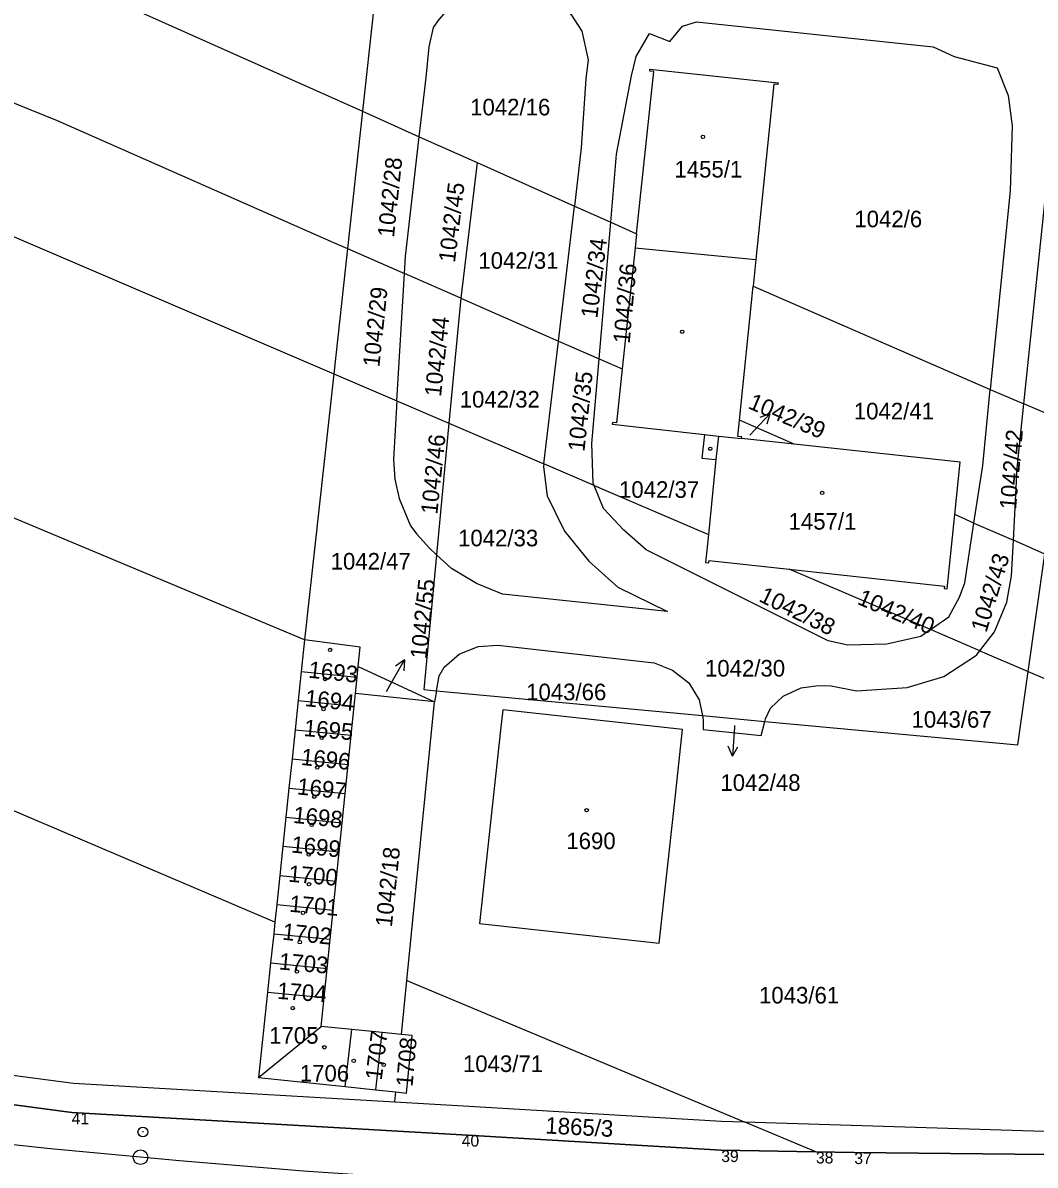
# Model space of a CAD drawing. Extents: x -779330 to -774454, y -1144748 to -1142831.
# Drawn here: x -775422.9 to -775319.2, y -1144462.2 to -1144345.1 of the extents above; entities that cross this region are included whole.
import ezdxf

# ---------------------------------------------------------------- set-up
doc = ezdxf.new("R2010")
doc.units = 0
for name, color, linetype in [('Hranice parcel', 7, 'Continuous'), ('Parcelní čísla', 7, 'Continuous'), ('Pop  PČ popisy', 7, 'Continuous'), ('SŽDC', 7, 'Continuous'), ('Vnitřní kresba', 7, 'Continuous'), ('Vrstva 1', 7, 'Continuous'), ('Vrstva 53', 7, 'Continuous'), ('Vrstva 60', 7, 'Continuous'), ('Vrstva 7', 7, 'Continuous'), ('Značky budov', 7, 'Continuous')]:
    doc.layers.add(name, color=color, linetype=linetype)

msp = doc.modelspace()

# ---------------------------------------------------------------- linework, layer by layer
at = {"layer": 'Hranice parcel'}
for p, q in [((-775388.13, -1144354.18), (-775389.67, -1144368.26)), ((-775388.13, -1144354.18), (-775382.3, -1144356.79)), ((-775382.3, -1144356.79), (-775376.38, -1144359.43)), ((-775376.38, -1144359.43), (-775378.05, -1144373.35)), ((-775376.38, -1144359.43), (-775366.41, -1144363.89)), ((-775368.04, -1144377.73), (-775366.41, -1144363.89)), ((-775366.41, -1144363.89), (-775362.68, -1144365.56)), ((-775363.88, -1144379.55), (-775362.68, -1144365.56)), ((-775362.68, -1144365.56), (-775360.03, -1144366.75)), ((-775389.67, -1144368.26), (-775391.08, -1144381.09)), ((-775389.67, -1144368.26), (-775383.83, -1144370.82)), ((-775384.59, -1144383.87), (-775383.83, -1144370.82)), ((-775378.05, -1144373.35), (-775383.83, -1144370.82)), ((-775349.49, -1144385.85), (-775348.09, -1144372.09)), ((-775348.09, -1144372.09), (-775323.77, -1144382.71)), ((-775378.05, -1144373.35), (-775379.26, -1144386.15)), ((-775378.05, -1144373.35), (-775368.04, -1144377.73)), ((-775369.53, -1144390.33), (-775368.04, -1144377.73)), ((-775368.04, -1144377.73), (-775363.88, -1144379.55)), ((-775363.88, -1144379.55), (-775361.5, -1144380.59)), ((-775391.08, -1144381.09), (-775394.06, -1144408.34)), ((-775391.08, -1144381.09), (-775384.59, -1144383.87)), ((-775323.77, -1144382.71), (-775320.33, -1144384.17)), ((-775384.59, -1144383.87), (-775379.26, -1144386.15)), ((-775317.45, -1144385.39), (-775320.33, -1144384.17)), ((-775379.26, -1144386.15), (-775380.53, -1144399.63)), ((-775379.26, -1144386.15), (-775369.53, -1144390.33)), ((-775343.88, -1144388.31), (-775349.49, -1144385.85)), ((-775343.88, -1144388.31), (-775349.26, -1144387.73)), ((-775364.38, -1144392.54), (-775369.53, -1144390.33)), ((-775364.38, -1144392.54), (-775352.65, -1144397.57)), ((-775325.45, -1144396.38), (-775327.4, -1144395.52)), ((-775325.45, -1144396.38), (-775321.4, -1144398.15)), ((-775318.18, -1144399.56), (-775321.4, -1144398.15)), ((-775329.91, -1144407.31), (-775344.4, -1144401.1)), ((-775324.84, -1144409.48), (-775329.91, -1144407.31)), ((-775394.06, -1144408.34), (-775394.4, -1144411.6)), ((-775324.84, -1144409.48), (-775319.89, -1144411.6)), ((-775394.4, -1144411.6), (-775394.72, -1144414.58)), ((-775394.4, -1144411.6), (-775388.68, -1144412.17)), ((-775388.68, -1144412.17), (-775388.57, -1144411.1)), ((-775388.57, -1144411.1), (-775380.75, -1144414.72)), ((-775319.89, -1144411.6), (-775313.07, -1144414.53)), ((-775388.84, -1144413.84), (-775388.68, -1144412.17)), ((-775388.98, -1144415.16), (-775388.84, -1144413.84)), ((-775380.75, -1144414.72), (-775388.84, -1144413.84)), ((-775380.54, -1144413.57), (-775380.75, -1144414.72)), ((-775380.54, -1144413.57), (-775353.29, -1144416.11)), ((-775394.72, -1144414.58), (-775395.03, -1144417.57)), ((-775394.72, -1144414.58), (-775388.98, -1144415.16)), ((-775389.29, -1144418.14), (-775388.98, -1144415.16)), ((-775383.57, -1144443.27), (-775380.75, -1144414.72)), ((-775353.29, -1144416.11), (-775346.87, -1144416.71)), ((-775395.03, -1144417.57), (-775395.35, -1144420.56)), ((-775395.03, -1144417.57), (-775389.29, -1144418.14)), ((-775389.59, -1144421.13), (-775389.29, -1144418.14)), ((-775395.35, -1144420.56), (-775395.66, -1144423.55)), ((-775395.35, -1144420.56), (-775389.59, -1144421.13)), ((-775389.9, -1144424.12), (-775389.59, -1144421.13)), ((-775395.66, -1144423.55), (-775395.97, -1144426.53)), ((-775395.66, -1144423.55), (-775389.9, -1144424.12)), ((-775390.2, -1144427.1), (-775389.9, -1144424.12)), ((-775395.97, -1144426.53), (-775396.29, -1144429.52)), ((-775395.97, -1144426.53), (-775390.2, -1144427.1)), ((-775390.52, -1144430.09), (-775390.2, -1144427.1)), ((-775396.29, -1144429.52), (-775396.6, -1144432.51)), ((-775396.29, -1144429.52), (-775390.52, -1144430.09)), ((-775390.82, -1144433.08), (-775390.52, -1144430.09)), ((-775396.6, -1144432.51), (-775396.92, -1144435.49)), ((-775396.6, -1144432.51), (-775390.82, -1144433.08)), ((-775391.12, -1144436.06), (-775390.82, -1144433.08)), ((-775396.92, -1144435.49), (-775397.11, -1144437.29)), ((-775396.92, -1144435.49), (-775391.12, -1144436.06)), ((-775391.44, -1144439.04), (-775391.12, -1144436.06)), ((-775397.11, -1144437.29), (-775397.23, -1144438.48)), ((-775397.23, -1144438.48), (-775397.55, -1144441.47)), ((-775397.23, -1144438.48), (-775391.44, -1144439.04)), ((-775391.74, -1144442.03), (-775391.44, -1144439.04)), ((-775397.55, -1144441.47), (-775397.86, -1144444.46)), ((-775397.55, -1144441.47), (-775391.74, -1144442.03)), ((-775392.05, -1144445.02), (-775391.74, -1144442.03)), ((-775384.12, -1144448.81), (-775383.57, -1144443.27)), ((-775383.57, -1144443.27), (-775348.99, -1144457.75)), ((-775397.86, -1144444.46), (-775398.78, -1144453.2)), ((-775397.86, -1144444.46), (-775392.05, -1144445.02)), ((-775392.35, -1144448), (-775392.05, -1144445.02)), ((-775398.78, -1144453.2), (-775392.35, -1144448)), ((-775389.23, -1144448.31), (-775392.35, -1144448)), ((-775389.89, -1144454.15), (-775389.23, -1144448.31)), ((-775386.1, -1144448.62), (-775389.23, -1144448.31)), ((-775386.75, -1144454.48), (-775386.1, -1144448.62)), ((-775384.12, -1144448.81), (-775386.1, -1144448.62)), ((-775398.78, -1144453.2), (-775389.89, -1144454.15)), ((-775389.89, -1144454.15), (-775386.75, -1144454.48)), ((-775386.75, -1144454.48), (-775384.7, -1144454.7)), ((-775384.8, -1144455.7), (-775384.7, -1144454.7)), ((-775348.99, -1144457.75), (-775318.25, -1144458.71)), ((-775341.64, -1144460.83), (-775348.99, -1144457.75))]:
    msp.add_line(p, q, dxfattribs=at)
for points in [[(-775607.93, -1144251.93), (-775592.73, -1144265.24), (-775577.44, -1144273.94), (-775563.67, -1144281.5), (-775543.76, -1144290.79), (-775411.19, -1144343.87), (-775388.13, -1144354.18)], [(-775632.59, -1144258.06), (-775621.58, -1144265.67), (-775577.27, -1144289.87), (-775522.49, -1144313.33), (-775419.42, -1144355.11), (-775391.09, -1144367.64), (-775389.67, -1144368.26)], [(-775657.22, -1144264.36), (-775641.76, -1144273.65), (-775618.95, -1144284.54), (-775447.05, -1144357.1), (-775391.08, -1144381.09)], [(-775394.06, -1144408.34), (-775619.55, -1144313.89), (-775660.82, -1144292.56), (-775671.23, -1144286.27), (-775688.22, -1144274.1)], [(-775397.11, -1144437.29), (-775575.13, -1144361.42), (-775643.03, -1144333.5), (-775681.69, -1144314.82), (-775705.2, -1144302.37), (-775726.91, -1144287.21)], [(-775352.89, -1144334.93), (-775353.07, -1144336.72), (-775363.07, -1144335.42), (-775385.03, -1144333.14), (-775385.87, -1144333.51), (-775388.13, -1144354.18)], [(-775382.3, -1144356.79), (-775381.59, -1144350.71), (-775381.29, -1144347.59), (-775380.83, -1144345.6), (-775380.26, -1144344.77), (-775379.26, -1144343.66), (-775378.34, -1144342.94), (-775376.9, -1144342.31), (-775374.94, -1144341.74), (-775371.99, -1144341.37), (-775370.97, -1144341.43), (-775368.36, -1144342.85), (-775366.76, -1144344.24), (-775365.64, -1144345.98), (-775364.98, -1144348.92), (-775365.24, -1144350.84), (-775365.71, -1144357.91), (-775366.41, -1144363.89)], [(-775362.68, -1144365.56), (-775362.08, -1144358.58), (-775360.56, -1144350.54), (-775360.06, -1144348.55), (-775358.72, -1144346.19), (-775356.63, -1144347.01), (-775355.33, -1144345.46), (-775353.88, -1144345), (-775329.64, -1144347.57), (-775327.49, -1144348.55), (-775323.08, -1144349.72), (-775321.94, -1144352.56), (-775321.52, -1144355.68), (-775321.75, -1144362.33), (-775323.77, -1144382.71)], [(-775360.03, -1144366.75), (-775358.26, -1144350.1), (-775358.68, -1144350.06), (-775358.66, -1144349.86), (-775345.53, -1144351.28), (-775345.55, -1144351.45), (-775345.97, -1144351.4), (-775347.81, -1144369.38), (-775348.09, -1144372.09)], [(-775320.33, -1144384.17), (-775318.15, -1144363.22), (-775316.68, -1144354.8), (-775314.36, -1144350.65), (-775311.52, -1144351.07), (-775309.28, -1144350.28), (-775307.1, -1144350.08), (-775278.88, -1144352.91), (-775272.68, -1144353.77), (-775264.39, -1144354.9), (-775253.71, -1144357.11), (-775245.99, -1144358.92)], [(-775383.83, -1144370.82), (-775383.73, -1144369.08), (-775382.3, -1144356.79)], [(-775360.03, -1144366.75), (-775360.18, -1144368.18), (-775361.5, -1144380.59)], [(-775364.38, -1144392.54), (-775364.48, -1144392.29), (-775364.63, -1144388.23), (-775363.88, -1144379.55)], [(-775361.5, -1144380.59), (-775362.09, -1144386.13), (-775362.51, -1144386.08), (-775362.52, -1144386.26), (-775353.06, -1144387.31)], [(-775325.45, -1144396.38), (-775324.54, -1144390.49), (-775323.77, -1144382.71)], [(-775384.59, -1144383.87), (-775384.94, -1144389.87), (-775384.8, -1144391.89), (-775384.35, -1144393.86), (-775383.2, -1144396.68), (-775382.56, -1144397.52), (-775381.24, -1144398.97), (-775380.53, -1144399.63)], [(-775321.4, -1144398.15), (-775321.01, -1144390.75), (-775320.33, -1144384.17)], [(-775349.26, -1144387.73), (-775349.24, -1144387.55), (-775349.66, -1144387.5), (-775349.49, -1144385.85)], [(-775353.06, -1144387.31), (-775353.33, -1144389.73), (-775351.89, -1144389.87), (-775352.65, -1144397.57)], [(-775353.06, -1144387.31), (-775351.65, -1144387.47), (-775349.26, -1144387.73)], [(-775327.4, -1144395.52), (-775326.85, -1144390.15), (-775343.88, -1144388.31)], [(-775369.53, -1144390.33), (-775369.56, -1144390.62), (-775369.2, -1144393.61), (-775367.43, -1144397.22), (-775364.92, -1144400.28), (-775361.96, -1144402.96), (-775356.85, -1144405.46), (-775373.79, -1144403.67), (-775376.43, -1144402.59), (-775378.99, -1144401.06), (-775380.53, -1144399.63)], [(-775329.91, -1144407.31), (-775330.89, -1144408), (-775334.37, -1144408.8), (-775338.37, -1144408.89), (-775340.4, -1144408.45), (-775359.06, -1144399.13), (-775361.34, -1144397.12), (-775363.43, -1144394.91), (-775364.38, -1144392.54)], [(-775344.4, -1144401.1), (-775328.46, -1144402.84), (-775328.49, -1144403.09), (-775328.19, -1144403.13), (-775327.4, -1144395.52)], [(-775329.91, -1144407.31), (-775328.04, -1144405.99), (-775326.93, -1144403.97), (-775326.4, -1144402.5), (-775325.45, -1144396.38)], [(-775352.65, -1144397.57), (-775352.95, -1144400.44), (-775352.62, -1144400.47), (-775352.59, -1144400.21), (-775344.4, -1144401.1)], [(-775324.84, -1144409.48), (-775323.33, -1144407.52), (-775322.07, -1144404.48), (-775321.59, -1144401.79), (-775321.4, -1144398.15)], [(-775380.53, -1144399.63), (-775381.84, -1144413.45), (-775380.54, -1144413.57)], [(-775388.57, -1144411.1), (-775388.36, -1144409.09), (-775394.06, -1144408.34)], [(-775380.54, -1144413.57), (-775380.26, -1144412.04), (-775379.75, -1144411.14), (-775378.21, -1144409.82), (-775376.28, -1144409.05), (-775374.25, -1144408.91), (-775358.23, -1144410.71), (-775356.36, -1144411.47), (-775354.67, -1144412.76), (-775353.62, -1144414.5), (-775353.29, -1144416.11)], [(-775346.87, -1144416.71), (-775346.8, -1144416.45), (-775346.3, -1144415.37), (-775344.99, -1144414.12), (-775343.17, -1144413.29), (-775341.43, -1144413.02), (-775340.07, -1144413.06), (-775337.49, -1144413.57), (-775332.31, -1144413.25), (-775328.54, -1144412.12), (-775325.18, -1144409.92), (-775324.84, -1144409.48)], [(-775346.87, -1144416.71), (-775320.96, -1144419.12), (-775319.89, -1144411.6)], [(-775355.32, -1144417.54), (-775373.75, -1144415.54), (-775373.98, -1144417.62), (-775376.13, -1144437.44), (-775357.7, -1144439.44), (-775356.16, -1144425.25), (-775355.32, -1144417.54)], [(-775353.29, -1144416.11), (-775353.2, -1144416.54), (-775353.2, -1144417.56), (-775347.25, -1144418.15), (-775346.87, -1144416.71)], [(-775384.7, -1144454.7), (-775383.62, -1144454.82), (-775383.02, -1144448.92), (-775384.12, -1144448.81)], [(-775436.47, -1144451.33), (-775417.75, -1144453.81), (-775384.8, -1144455.7)], [(-775341.64, -1144460.83), (-775351.35, -1144460.68), (-775377.95, -1144459.1), (-775417.93, -1144456.81), (-775426.17, -1144455.72)], [(-775384.8, -1144455.7), (-775377.77, -1144456.11), (-775351.31, -1144457.68), (-775348.99, -1144457.75)], [(-775254.16, -1144459.9), (-775301.48, -1144461.27), (-775337.71, -1144460.89), (-775341.64, -1144460.83)]]:
    msp.add_lwpolyline(points, dxfattribs=at)
at = {"layer": 'Pop  PČ popisy'}
for p, q in [((-775348.41, -1144387.37), (-775346.36, -1144385.18)), ((-775346.36, -1144385.18), (-775347.41, -1144385.57)), ((-775346.36, -1144385.18), (-775346.68, -1144386.25)), ((-775348.42, -1144387.38), (-775348.41, -1144387.37)), ((-775385.31, -1144413.02), (-775383.81, -1144410.42)), ((-775383.81, -1144410.42), (-775384.74, -1144411.04)), ((-775383.81, -1144410.42), (-775383.88, -1144411.54)), ((-775385.68, -1144413.64), (-775385.31, -1144413.02)), ((-775350, -1144417.29), (-775350.21, -1144420.28)), ((-775349.99, -1144417.13), (-775350, -1144417.29)), ((-775350.21, -1144420.28), (-775350.64, -1144419.25)), ((-775350.21, -1144420.28), (-775349.64, -1144419.32))]:
    msp.add_line(p, q, dxfattribs=at)
at = {"layer": 'SŽDC'}
msp.add_lwpolyline([(-774890.46, -1144432.61), (-774957.77, -1144437.47), (-775003.31, -1144440.57), (-775006.9, -1144440.82), (-775032.95, -1144440.83), (-775037.63, -1144440.85), (-775036.16, -1144437.94), (-775069.78, -1144440.38), (-775071.04, -1144440.88), (-775088.39, -1144447.82), (-775138.01, -1144449.91), (-775170.99, -1144453.66), (-775254.16, -1144459.9), (-775301.48, -1144461.27), (-775337.71, -1144460.89), (-775341.64, -1144460.83), (-775351.35, -1144460.68), (-775377.95, -1144459.1), (-775417.93, -1144456.81), (-775426.17, -1144455.72)], dxfattribs=at)
at = {"layer": 'Vnitřní kresba'}
for p, q in [((-775360.18, -1144368.18), (-775347.81, -1144369.38)), ((-775351.65, -1144387.47), (-775351.89, -1144389.87)), ((-775319.89, -1144411.6), (-775318.18, -1144399.56))]:
    msp.add_line(p, q, dxfattribs=at)
at = {"layer": 'Vrstva 1'}
msp.add_lwpolyline([(-775237.52, -1144462.13), (-775254.42, -1144463.35), (-775267.45, -1144464.14), (-775280.95, -1144464.78), (-775295.68, -1144465.25), (-775309.68, -1144465.5), (-775323.38, -1144465.56), (-775336.76, -1144465.43), (-775349.91, -1144465.12), (-775359.65, -1144464.79), (-775367.99, -1144464.43), (-775381.03, -1144463.72), (-775394.17, -1144462.83), (-775406.88, -1144461.77), (-775420.1, -1144460.52), (-775432.46, -1144459.19)], dxfattribs=at)
at = {"layer": 'Vrstva 53'}
msp.add_lwpolyline([(-775426.17, -1144455.72), (-775417.93, -1144456.81), (-775377.95, -1144459.1), (-775351.35, -1144460.68), (-775341.64, -1144460.83), (-775337.71, -1144460.89), (-775301.48, -1144461.27), (-775254.16, -1144459.9), (-775170.99, -1144453.66), (-775138.01, -1144449.91), (-775088.39, -1144447.82), (-775071.04, -1144440.88), (-775069.78, -1144440.38), (-775036.16, -1144437.94), (-775037.63, -1144440.85), (-775032.95, -1144440.83), (-775006.9, -1144440.82), (-775003.31, -1144440.57), (-774957.77, -1144437.47), (-774890.46, -1144432.61)], dxfattribs=at)
msp.add_lwpolyline([(-775426.17, -1144455.72), (-775417.93, -1144456.81), (-775377.95, -1144459.1), (-775351.35, -1144460.68), (-775341.64, -1144460.83), (-775337.71, -1144460.89), (-775301.48, -1144461.27), (-775254.16, -1144459.9), (-775170.99, -1144453.66), (-775138.01, -1144449.91), (-775088.39, -1144447.82), (-775071.04, -1144440.88), (-775069.78, -1144440.38), (-775036.16, -1144437.94), (-775037.63, -1144440.85), (-775032.95, -1144440.83), (-775006.9, -1144440.82), (-775003.31, -1144440.57), (-774957.77, -1144437.47), (-774890.46, -1144432.61)], dxfattribs=at)
at = {"layer": 'Vrstva 60'}
for p, q in [((-775417.93, -1144456.81), (-775417.93, -1144456.81)), ((-775377.95, -1144459.1), (-775377.95, -1144459.1)), ((-775351.35, -1144460.68), (-775351.35, -1144460.68)), ((-775341.64, -1144460.83), (-775341.64, -1144460.83)), ((-775337.71, -1144460.89), (-775337.71, -1144460.89))]:
    msp.add_line(p, q, dxfattribs=at)
at = {"layer": 'Vrstva 7'}
msp.add_line((-775410.59, -1144458.8), (-775410.69, -1144458.79), dxfattribs=at)
for centre, radius in [((-775410.64, -1144458.8), 0.5), ((-775410.88, -1144461.39), 0.75)]:
    msp.add_circle(centre, radius, dxfattribs=at)
at = {"layer": 'Značky budov'}
for centre in [(-775353.23, -1144356.8), (-775355.36, -1144376.78), (-775352.48, -1144388.77), (-775341.01, -1144393.3), (-775391.45, -1144409.39), (-775391.96, -1144412.38), (-775392.12, -1144415.45), (-775392.3, -1144418.41), (-775392.76, -1144421.45), (-775393.07, -1144424.44), (-775365.15, -1144425.82), (-775393.33, -1144427.33), (-775393.63, -1144430.37), (-775393.61, -1144433.41), (-775394.23, -1144436.34), (-775394.55, -1144439.34), (-775394.85, -1144442.36), (-775395.27, -1144446.1), (-775392.04, -1144450.12), (-775389.03, -1144451.51), (-775385.95, -1144451.92)]:
    msp.add_circle(centre, 0.175, dxfattribs=at)

# ---------------------------------------------------------------- texts
at = {"layer": 'Parcelní čísla'}
for s, p in [('1042/16', (-775377.09, -1144354.6)), ('1455/1', (-775356.15, -1144360.97)), ('1042/6', (-775337.71, -1144366.07)), ('1042/31', (-775376.25, -1144370.32)), ('1042/32', (-775378.16, -1144384.55)), ('1042/41', (-775337.76, -1144385.76)), ('1042/37', (-775361.83, -1144393.8)), ('1457/1', (-775344.45, -1144397.06)), ('1042/33', (-775378.33, -1144398.77)), ('1042/47', (-775391.39, -1144401.15)), ('1042/30', (-775353.02, -1144412.12)), ('1043/66', (-775371.35, -1144414.55)), ('1043/67', (-775331.85, -1144417.36)), ('1042/48', (-775351.44, -1144423.84)), ('1690', (-775367.23, -1144429.81)), ('1043/61', (-775347.48, -1144445.63)), ('1705', (-775397.69, -1144449.75)), ('1043/71', (-775377.83, -1144452.65)), ('1706', (-775394.55, -1144453.63))]:
    msp.add_text(s, height=1.7, dxfattribs=at).set_placement(p)
for s, rotation, p in [('1042/28', 84, (-775384.9, -1144367.16)), ('1042/45', 83, (-775378.65, -1144369.74)), ('1042/34', 83, (-775364.06, -1144375.45)), ('1042/36', 85, (-775360.74, -1144378.03)), ('1042/29', 84, (-775386.4, -1144380.45)), ('1042/44', 84, (-775380.08, -1144383.49)), ('1042/35', 84, (-775365.38, -1144389.11)), ('1042/39', 337, (-775348.7, -1144384.59)), ('1042/46', 84, (-775380.46, -1144395.55)), ('1042/42', 85, (-775321.14, -1144395.06)), ('1042/43', 73, (-775324.18, -1144407.68)), ('1042/55', 84, (-775381.55, -1144410.38)), ('1042/38', 334, (-775347.6, -1144404.36)), ('1042/40', 337, (-775337.51, -1144404.65)), ('1693', 354, (-775393.72, -1144412.23)), ('1694', 354, (-775394.08, -1144415.14)), ('1695', 355, (-775394.19, -1144418.21)), ('1696', 354, (-775394.49, -1144421.17)), ('1697', 354, (-775394.88, -1144424.19)), ('1698', 354, (-775395.29, -1144427.11)), ('1699', 354, (-775395.48, -1144430.14)), ('1042/18', 84, (-775385.12, -1144437.85)), ('1700', 355, (-775395.78, -1144433.14)), ('1701', 355, (-775395.67, -1144436.22)), ('1702', 354, (-775396.4, -1144439.08)), ('1703', 355, (-775396.74, -1144442.13)), ('1704', 356, (-775396.91, -1144445.15)), ('1707', 83, (-775386.16, -1144453.55)), ('1708', 85, (-775383, -1144454.21)), ('1865/3', 357, (-775369.41, -1144458.95))]:
    msp.add_text(s, height=1.7, rotation=rotation, dxfattribs=at).set_placement(p)
at = {"layer": 'Vrstva 60'}
for s, p in [('41', (-775417.93, -1144458.01)), ('40', (-775377.95, -1144460.3)), ('39', (-775351.35, -1144461.88)), ('38', (-775341.64, -1144462.03)), ('37', (-775337.71, -1144462.09))]:
    msp.add_text(s, height=1.2, dxfattribs=at).set_placement(p)

doc.saveas('drawing.dxf')
